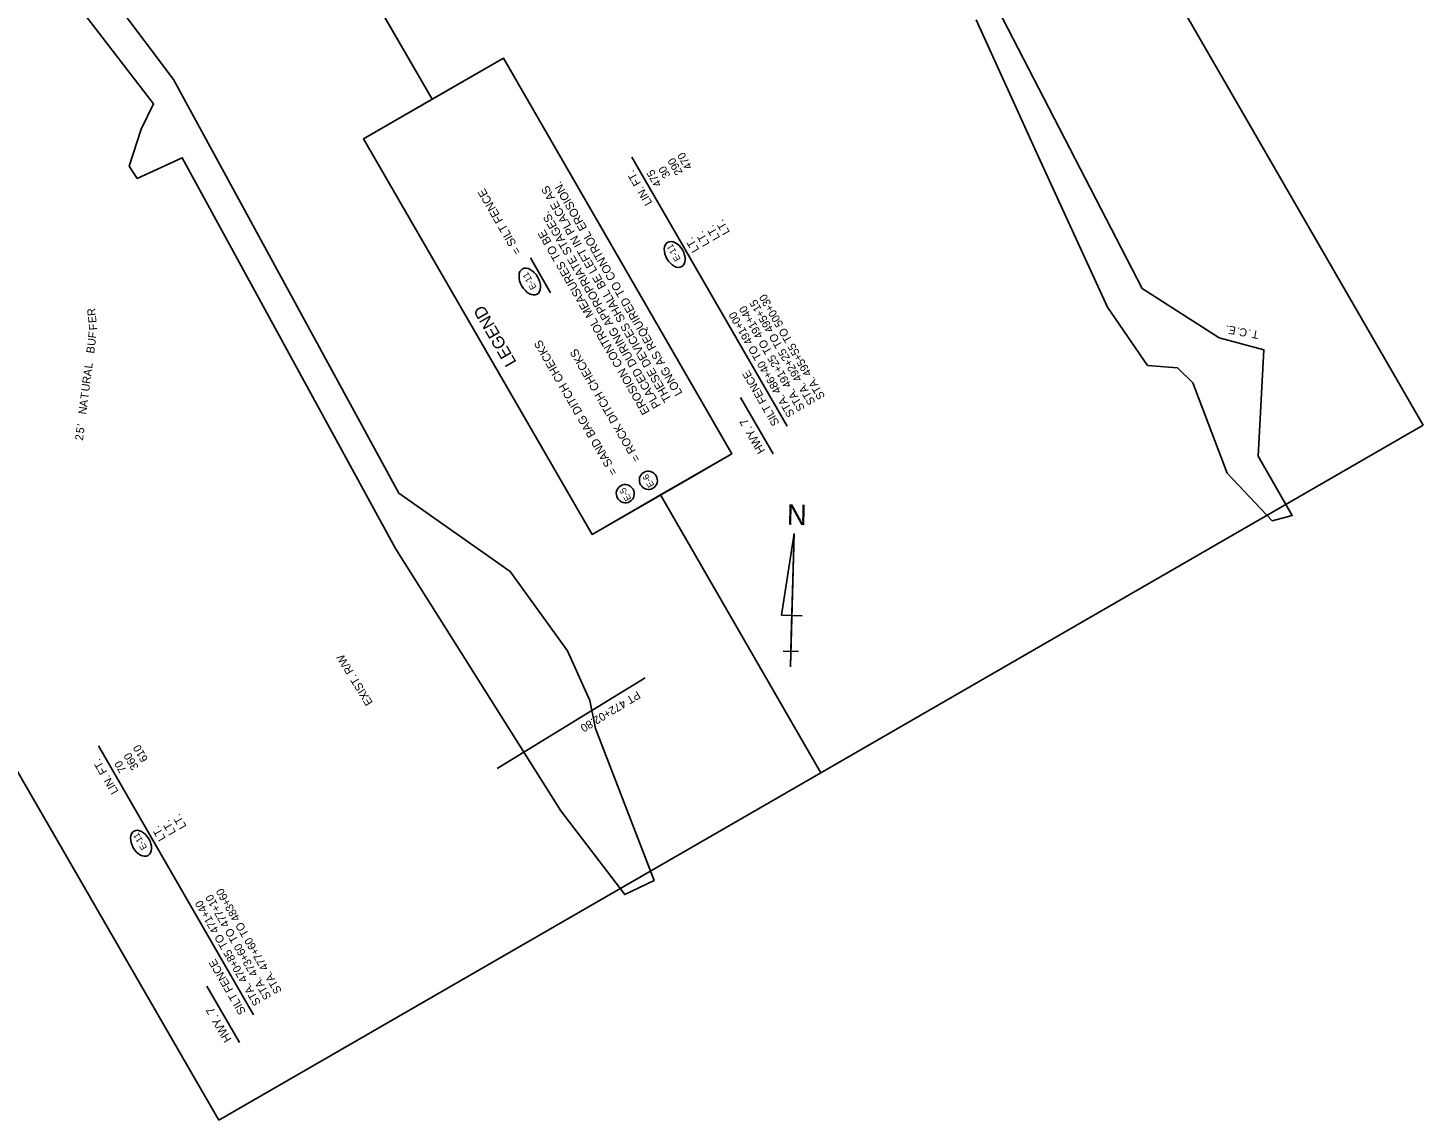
# Model space of a CAD drawing. Extents: x 956270 to 957915, y 1920520 to 1922423.
# Drawn here: x 956869 to 957915, y 1920520 to 1921340 of the extents above; entities that cross this region are included whole.
import ezdxf

# ---------------------------------------------------------------- set-up
doc = ezdxf.new("R2010")
doc.units = 0
for name, color, linetype in [('1', 7, 'Continuous'), ('44', 7, 'Continuous'), ('63', 7, 'Continuous'), ('Level 1', 7, 'Continuous'), ('Level 44', 7, 'Continuous'), ('NO PLOT', 7, 'Continuous'), ('R_Draft', 7, 'Continuous'), ('R_Horz Alg Annot', 7, 'Continuous')]:
    doc.layers.add(name, color=color, linetype=linetype)

msp = doc.modelspace()

# ---------------------------------------------------------------- linework, layer by layer
at = {"layer": '1'}
for p, q in [((957172.3, 1921286.1), (957029.2, 1921533.9)), ((957225.7, 1921317), (957120.9, 1921256.4)), ((957292.2, 1920959.7), (957120.9, 1921256.4)), ((957367.7, 1921003.2), (957292.2, 1920959.7)), ((957463.8, 1920781), (957343.6, 1920989.3))]:
    msp.add_line(p, q, dxfattribs=at)
msp.add_lwpolyline([(957367.7, 1921003.2), (957397.1, 1921020.2), (957225.7, 1921317)], dxfattribs=at)
for centre in [(957354.2, 1921169.7), (956954.1, 1920728.1)]:
    msp.add_ellipse(centre, major_axis=(-5.26, 9.11), ratio=0.638788, dxfattribs=at)
at = {"layer": '44'}
for p, q in [((957438.5, 1921041), (957322.1, 1921242.6)), ((957427.9, 1921020.2), (957403.5, 1921062.5)), ((957038.5, 1920599.4), (956922.1, 1920801.1)), ((957027.9, 1920578.7), (957003.5, 1920621))]:
    msp.add_line(p, q, dxfattribs=at)
at = {"layer": '63'}
for p, q in [((957443.6, 1920960.4), (957434.3, 1920899.1)), ((957440.9, 1920860.4), (957443.6, 1920960.4)), ((957443.6, 1920960.4), (957441.5, 1920883.5)), ((957434.3, 1920899.1), (957449.6, 1920898.7)), ((957440.9, 1920860.4), (957441.5, 1920883.5)), ((957441.2, 1920872), (957435.5, 1920872.1)), ((957435.5, 1920872.1), (957447, 1920871.8)), ((957440.9, 1920860.4), (957441.2, 1920872))]:
    msp.add_line(p, q, dxfattribs=at)
at = {"layer": 'Level 1'}
for centre, major_axis, ratio in [((957245.5, 1921149.4), (-5.48, 9.49), 0.622952), ((957334.4, 1921000.3), (3.44, -5.96), 0.97521), ((957317.1, 1920990.3), (3.44, -5.96), 0.97521)]:
    msp.add_ellipse(centre, major_axis=major_axis, ratio=ratio, dxfattribs=at)
at = {"layer": 'Level 44'}
msp.add_lwpolyline([(957261.1, 1921141), (957246, 1921167.1)], dxfattribs=at)
at = {"layer": 'NO PLOT'}
for points in [[(957915.2, 1921041.6), (957117.5, 1922423.2), (956666.2, 1922162.6), (956816.7, 1921902), (956875.1, 1921935.7), (957087.6, 1921567.7), (957029.2, 1921533.9), (957172.3, 1921286.1), (957225.7, 1921317), (957397.1, 1921020.2), (957343.6, 1920989.3), (957463.8, 1920781)], [(957915.2, 1921041.6), (957117.5, 1922423.2), (956666.2, 1922162.6), (956816.7, 1921902), (956875.1, 1921935.7), (957087.6, 1921567.7), (957029.2, 1921533.9), (957172.3, 1921286.1), (957225.7, 1921317), (957397.1, 1921020.2), (957343.6, 1920989.3), (957463.8, 1920781)], [(957915.2, 1921041.6), (957117.5, 1922423.2), (956666.2, 1922162.6), (956816.7, 1921902), (956875.1, 1921935.7), (957087.6, 1921567.7), (957029.2, 1921533.9), (957172.3, 1921286.1), (957225.7, 1921317), (957397.1, 1921020.2), (957343.6, 1920989.3), (957463.8, 1920781)], [(957012.5, 1920520.4), (956420.5, 1921545.9), (956463.3, 1921570.6), (956365.4, 1921740.1), (956378, 1921747.4), (956270.3, 1921934.1), (956666.2, 1922162.6), (956816.7, 1921902), (956750, 1921863.5), (956962.5, 1921495.4), (957029.2, 1921533.9), (957172.3, 1921286.1), (957120.9, 1921256.4), (957292.2, 1920959.7), (957343.6, 1920989.3), (957463.8, 1920781)], [(957012.5, 1920520.4), (956420.5, 1921545.9), (956463.3, 1921570.6), (956365.4, 1921740.1), (956378, 1921747.4), (956270.3, 1921934.1), (956666.2, 1922162.6), (956816.7, 1921902), (956750, 1921863.5), (956962.5, 1921495.4), (957029.2, 1921533.9), (957172.3, 1921286.1), (957120.9, 1921256.4), (957292.2, 1920959.7), (957343.6, 1920989.3), (957463.8, 1920781)], [(957012.5, 1920520.4), (956420.5, 1921545.9), (956463.3, 1921570.6), (956365.4, 1921740.1), (956378, 1921747.4), (956270.3, 1921934.1), (956666.2, 1922162.6), (956816.7, 1921902), (956750, 1921863.5), (956962.5, 1921495.4), (957029.2, 1921533.9), (957172.3, 1921286.1), (957120.9, 1921256.4), (957292.2, 1920959.7), (957343.6, 1920989.3), (957463.8, 1920781)]]:
    msp.add_lwpolyline(points, close=True, dxfattribs=at)
for points in [[(956883.9, 1921386.2), (956963.4, 1921282.8), (956954.1, 1921263.6), (956945.3, 1921236), (956951.3, 1921226.7), (956985, 1921242.2), (957144.9, 1920949.1), (957268.7, 1920752.5), (957316.7, 1920689.6), (957338.7, 1920700.2), (957294.8, 1920814.2), (957290.6, 1920835.1), (957273.8, 1920872.4), (957230.9, 1920931.8), (957147.3, 1920990.6), (956978.4, 1921301), (956892, 1921416.3)], [(957580.2, 1921345.8), (957625.4, 1921246.1), (957678.5, 1921130.2), (957708.7, 1921086.5), (957731, 1921084.7), (957742.6, 1921073.5), (957768.3, 1921005.6), (957802, 1920970), (957817.1, 1920973.9), (957791.5, 1921018.4), (957795.7, 1921098.2), (957762.4, 1921107.2), (957704.5, 1921144.2), (957596.2, 1921354.1)]]:
    msp.add_lwpolyline(points, dxfattribs=at)
at = {"layer": 'R_Horz Alg Annot'}
msp.add_lwpolyline([(957221.1, 1920784.2), (957332, 1920852.1)], dxfattribs=at)

# ---------------------------------------------------------------- texts
at = {"layer": '1'}
for p in [(957358.8, 1921166.3), (956958.8, 1920724.8)]:
    msp.add_text('E-11', height=4.8, rotation=120, dxfattribs=at).set_placement(p)
at = {"layer": '44'}
for s, height, p in [('470', 6, (957367.6, 1921235.4)), ('30', 6, (957351.2, 1921229)), ('290', 6, (957360.4, 1921231.3)), ('LIN. FT.', 6, (957337.5, 1921208.5)), ('475', 6, (957344.6, 1921222.4)), ('LT.', 6, (957395.7, 1921186.5)), ('LT.', 6, (957380.6, 1921177.8)), ('LT.', 6, (957388.4, 1921182.4)), ('LT.', 6, (957372.8, 1921173.3)), ('STA. 491+25 TO 491+40', 6, (957452, 1921054.3)), ('STA. 492+25 TO 495+15', 6, (957459.9, 1921058.9)), ('STA. 495+55 TO 500+30', 6, (957467.1, 1921063)), ('STA. 486+40 TO 491+00', 6, (957444.3, 1921049.8)), ('SILT FENCE      ', 6, (957432.9, 1921043.2)), ('HWY. 7', 6.25, (957422.2, 1921022.5)), ('610', 6, (956959.6, 1920791.1)), ('LIN. FT.', 6, (956937.4, 1920767)), ('70', 6, (956943.4, 1920783)), ('360', 6, (956952.6, 1920785.1)), ('LT.', 6, (956980.5, 1920736.3)), ('LT.', 6, (956988.4, 1920740.8)), ('LT.', 6, (956972.8, 1920731.8)), ('STA. 477+60 TO 483+60', 6, (957059.9, 1920617.3)), ('STA. 470+85 TO 471+40', 6, (957044.2, 1920608.3)), ('STA. 473+60 TO 477+10', 6, (957052, 1920612.8)), ('SILT FENCE      ', 6, (957032.9, 1920601.7)), ('HWY. 7', 6.25, (957022.2, 1920581))]:
    msp.add_text(s, height=height, rotation=120, dxfattribs=at).set_placement(p)
at = {"layer": '63'}
msp.add_text('N', height=15.4, rotation=358.5016, dxfattribs=at).set_placement((957438.1, 1920967))
at = {"layer": 'Level 1'}
for s, height, p in [('= SILT FENCE', 6.25, (957239.3, 1921171.7)), ('THESE DEVICES SHALL BE LEFT IN PLACE AS ', 6.25, (957352, 1921061.1)), ('LONG AS REQUIRED TO CONTROL EROSION.', 6.25, (957360.2, 1921065.8)), ('PLACED DURING APPROPRIATE STAGES. ', 6.25, (957343.9, 1921056.4)), ('EROSION CONTROL MEASURES TO BE', 6.25, (957335.7, 1921051.7)), ('E-11 ', 4.88, (957250.8, 1921145)), ('= SAND BAG DITCH CHECKS', 6.25, (957311.5, 1921006.2)), ('= ROCK DITCH CHECKS', 6.25, (957328.8, 1921016.2)), ('E-5 ', 4.88, (957321.8, 1920986.5)), ('E-6 ', 4.88, (957339, 1920996.7))]:
    msp.add_text(s, height=height, rotation=120, dxfattribs=at).set_placement(p)
at = {"layer": 'Level 44'}
msp.add_text('LEGEND', height=9.14, rotation=120, dxfattribs=at).set_placement((957235.8, 1921088.9))
at = {"layer": 'R_Draft'}
for s, rotation, p in [('R', 95.8222, (956920.2, 1921123.9)), ('E', 95.8222, (956920.8, 1921118.6)), ('F', 82.6936, (956920.3, 1921106.5)), ('F', 95.8222, (956921.3, 1921113.2)), ('.', 169.8911, (957769.9, 1921116.2)), ('E', 169.8911, (957775.2, 1921115.3)), ('.', 169.8911, (957778.1, 1921114.7)), ('C', 169.8911, (957783.7, 1921113.7)), ('.', 169.8911, (957786.6, 1921113.2)), ('T', 169.8911, (957792.3, 1921112.2)), ('B', 82.6936, (956918.9, 1921095.2)), ('U', 82.6936, (956919.6, 1921100.8)), ('A', 82.6936, (956916.7, 1921078.1)), ('L', 82.6936, (956917.4, 1921083.9)), ('U', 82.6936, (956915.2, 1921066.7)), ('R', 82.6936, (956915.9, 1921072.4)), ('A', 82.6936, (956913.7, 1921055.1)), ('T', 82.6936, (956914.5, 1921060.9)), ('N', 82.6936, (956913, 1921049.5)), ('5', 82.6936, (956911.2, 1921035.3)), ("'", 82.6936, (956911.9, 1921040.6)), ('2', 82.6936, (956910.5, 1921029.9)), ('EXIST. R/W', 121.503, (957128.1, 1920833.6))]:
    msp.add_text(s, height=6, rotation=rotation, dxfattribs=at).set_placement(p)
at = {"layer": 'R_Horz Alg Annot'}
msp.add_text('PT 472+02.80', height=6, rotation=211.4607, dxfattribs=at).set_placement((957326.1, 1920842.6))

doc.saveas('drawing.dxf')
